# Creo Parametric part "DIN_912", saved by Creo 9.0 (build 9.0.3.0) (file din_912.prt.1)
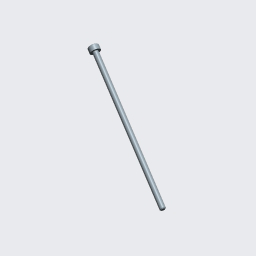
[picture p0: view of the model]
Units: Custom; MM, POUND, SECS

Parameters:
  BASIC_DIA = "0"
  PLACEMENT = "A"

Other parameters: D14, D1, D28, D3, D7, D4, D29, D46, THREADS_PER_INCH

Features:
  1. round
  2. datum plane "DTM1"
  3. datum plane "DTM2"
  4. cut
  5. round
  6. chamfer
  7. cut

Other named items: BLIND

Named dimensions: basic_dia, chmf

Layers: 1, 2, 3, 4, 5, 6, 7, 8, 9, 10, 11, 12, 13, 14, 15, 16, 17, 18, 19, 20, 21, 22, 23, 24, 25, 26, 27, 28, 29, 30, 31, 32, FLAECHEN, FLAECHENVERBUND, GEOM.ELEMENT, KONSTR.ELEMENT

Family table entries: DIN912M1_4, DIN_912, DIN912M1_4X2, DIN912M1_4, value(d_val), value(i_val), DIN912M1_4X2_5, DIN912M1_4, DIN912M1_4X3, DIN912M1_4, DIN912M1_4X4, DIN912M1_4, DIN912M1_4X5, DIN912M1_4, DIN912M1_4X6, DIN912M1_4, DIN912M1_4X8, DIN912M1_4, &/ , DIN912M1_4X10, DIN912M1_4, &/$, DIN912M1_4X12, DIN912M1_4, &/(, d45, value(s_val), 1_4, DIN912M1_6, DIN_912, DIN912M1_6X2_5, DIN912M1_6, DIN912M1_6X3, DIN912M1_6, DIN912M1_6X4, DIN912M1_6, DIN912M1_6X5, DIN912M1_6, DIN912M1_6X6, DIN912M1_6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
